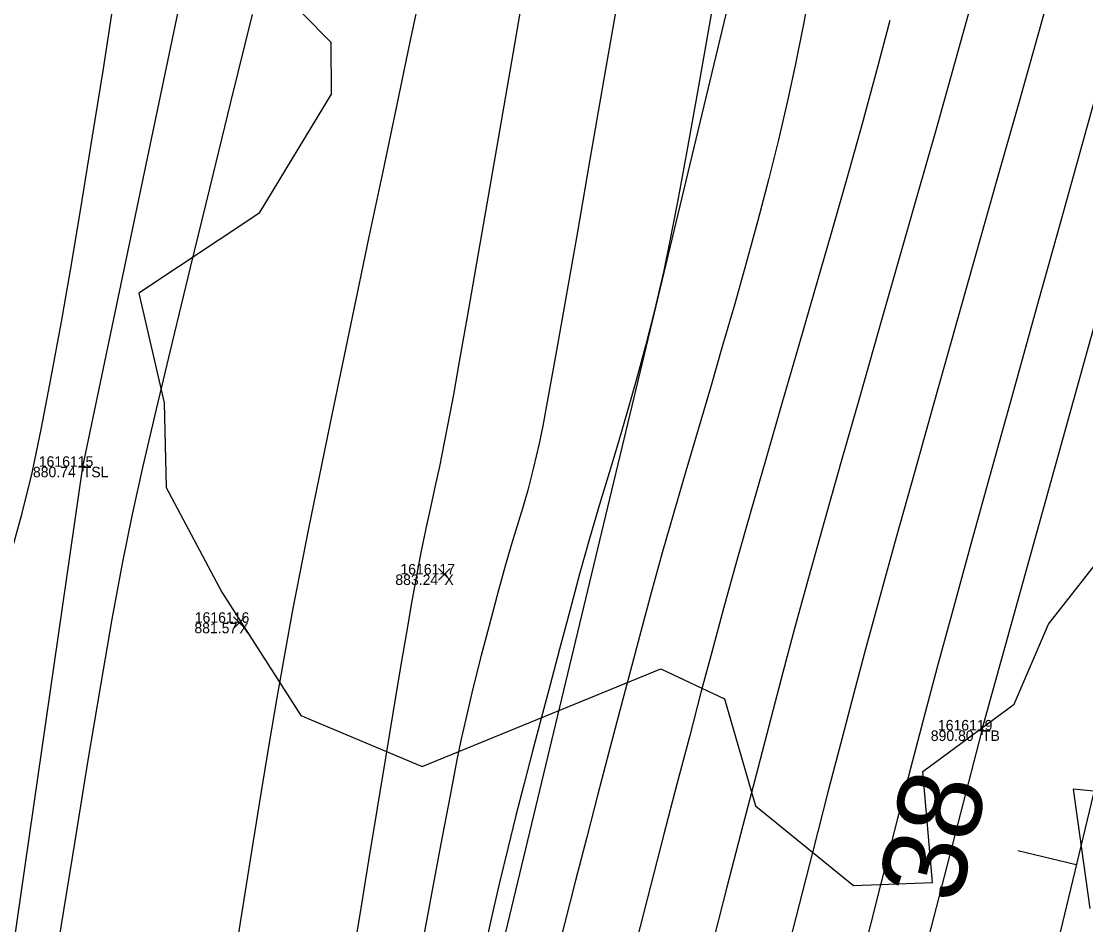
# Model space of a CAD drawing. Extents: x 1957117 to 1971063, y 701601 to 715861.
# Drawn here: x 1963216.28 to 1963251.82, y 705740.89 to 705771.05 of the extents above; entities that cross this region are included whole.
import ezdxf

# ---------------------------------------------------------------- set-up
doc = ezdxf.new("R2010")
doc.units = 0
for name, color, linetype in [('AP_X_Lights', 7, 'Continuous'), ('DT_X_Break_Line', 7, 'Continuous'), ('DT_X_Contour_Major', 7, 'Continuous'), ('DT_X_Contour_Minor', 7, 'Continuous'), ('GE_X_CL_20', 7, 'Continuous'), ('HY_X_Water_Edge', 7, 'Continuous'), ('PV_P_Drive', 7, 'Continuous'), ('PV_P_Shoulder', 7, 'Continuous'), ('RS_Raster1', 7, 'Continuous'), ('RW_X_Esmt_RR', 7, 'Continuous'), ('SC_Scratch1', 7, 'Continuous'), ('SC_Shading5', 7, 'Continuous'), ('VG_X_Tree_Line_Rt', 7, 'Continuous')]:
    doc.layers.add(name, color=color, linetype=linetype)

msp = doc.modelspace()

# ---------------------------------------------------------------- linework, layer by layer
at = {"layer": 'AP_X_Lights'}
for p, q in [((1963230.21, 705752.387), (1963230.598, 705752.777)), ((1963230.21, 705752.777), (1963230.598, 705752.387)), ((1963223.365, 705750.775), (1963223.753, 705751.165)), ((1963223.365, 705751.165), (1963223.753, 705750.775))]:
    msp.add_line(p, q, dxfattribs=at)
at = {"layer": 'DT_X_Break_Line'}
for points in [[(1963218.329, 705756.178), (1963229.265, 705808.356), (1963234.8, 705853.147), (1963240.079, 705903.468), (1963258.033, 705954.684), (1963270.287, 705999.321), (1963276.323, 706049.345), (1963291.502, 706096.678), (1963290.138, 706117.655), (1963319.921, 706191.295), (1963330.374, 706242.631), (1963344.413, 706289.409), (1963345.772, 706340.009), (1963383.117, 706434.704), (1963392.11, 706487.426), (1963408.164, 706535.687), (1963423.633, 706582.721), (1963435.242, 706630.63), (1963443.084, 706680.696), (1963464.732, 706726.815), (1963480.654, 706774.214), (1963508.465, 706799.669), (1963511.002, 706809.48)], [(1963248.355, 705747.376), (1963261.829, 705795.923), (1963267.581, 705840.559), (1963287.153, 705892.264), (1963291.083, 705944.763), (1963301.574, 705996.211), (1963311.528, 706039.027), (1963334.717, 706086.75), (1963331.957, 706106.508), (1963348.786, 706182.796), (1963365.664, 706223.934), (1963373.462, 706281.461), (1963387.853, 706330.217), (1963397.264, 706379.501), (1963407.696, 706427.592), (1963426.755, 706477.16), (1963442.136, 706524.014), (1963446.007, 706569.971), (1963489.391, 706666.839), (1963500.526, 706701.536)], [(1963059.618, 705072.384), (1963067.267, 705121.949), (1963084.435, 705172.155), (1963089.948, 705219.61), (1963104.733, 705267.194), (1963118.935, 705315.406), (1963122.413, 705362.88), (1963135.773, 705414.457), (1963142.701, 705466.671), (1963157.121, 705507.344), (1963171.033, 705561.75), (1963190.964, 705600.578), (1963199.065, 705656.682), (1963210.848, 705704.455), (1963218.329, 705756.178)], [(1963248.355, 705747.376), (1963235.759, 705698.829), (1963221.229, 705652.053), (1963207.844, 705601.615), (1963200.47, 705556.329), (1963185.917, 705507.018), (1963175.154, 705452.621), (1963160.398, 705408.434), (1963150.566, 705354.43), (1963137.351, 705306.484), (1963127.753, 705261.545), (1963117.087, 705216.019), (1963104.746, 705164.3), (1963091.28, 705116.393), (1963081.686, 705067.168)]]:
    msp.add_lwpolyline(points, dxfattribs=at)
at = {"layer": 'DT_X_Contour_Major'}
for points in [[(1963253.53, 705773.47), (1963252.693, 705770.482), (1963251.848, 705767.465), (1963251.009, 705764.466), (1963250.189, 705761.531), (1963249.403, 705758.709), (1963248.663, 705756.046), (1963247.984, 705753.59), (1963247.379, 705751.387), (1963246.862, 705749.484), (1963246.446, 705747.93), (1963246.036, 705746.364), (1963245.537, 705744.431), (1963244.96, 705742.179), (1963244.318, 705739.658), (1963243.623, 705736.92), (1963242.888, 705734.012), (1963242.124, 705730.985), (1963241.346, 705727.89), (1963240.563, 705724.775), (1963239.791, 705721.69), (1963239.039, 705718.686), (1963238.322, 705715.813)], [(1963253.53, 705773.47), (1963252.693, 705770.482), (1963251.848, 705767.465), (1963251.009, 705764.466), (1963250.189, 705761.531), (1963249.403, 705758.709), (1963248.663, 705756.046), (1963247.984, 705753.59), (1963247.379, 705751.387), (1963246.862, 705749.484), (1963246.446, 705747.93), (1963246.036, 705746.364), (1963245.537, 705744.431), (1963244.96, 705742.179), (1963244.318, 705739.658), (1963243.623, 705736.92), (1963242.888, 705734.012), (1963242.124, 705730.985), (1963241.346, 705727.89), (1963240.563, 705724.775), (1963239.791, 705721.69), (1963239.039, 705718.686), (1963238.322, 705715.813)], [(1963239.664, 705773.319), (1963239.246, 705770.907), (1963238.856, 705768.69), (1963238.501, 705766.713), (1963238.189, 705765.021), (1963237.926, 705763.659), (1963237.719, 705762.671), (1963237.42, 705761.392), (1963237.122, 705760.211), (1963236.822, 705759.102), (1963236.521, 705758.042), (1963236.216, 705757.007), (1963235.906, 705755.973), (1963235.589, 705754.916), (1963235.265, 705753.812), (1963234.932, 705752.638), (1963234.588, 705751.369), (1963234.25, 705750.093), (1963233.933, 705748.901), (1963233.633, 705747.771), (1963233.346, 705746.681), (1963233.068, 705745.61), (1963232.795, 705744.537), (1963232.524, 705743.439), (1963232.25, 705742.297), (1963231.97, 705741.087), (1963231.678, 705739.789)], [(1963239.664, 705773.319), (1963239.246, 705770.907), (1963238.856, 705768.69), (1963238.501, 705766.713), (1963238.189, 705765.021), (1963237.926, 705763.659), (1963237.719, 705762.671), (1963237.42, 705761.392), (1963237.122, 705760.211), (1963236.822, 705759.102), (1963236.521, 705758.042), (1963236.216, 705757.007), (1963235.906, 705755.973), (1963235.589, 705754.916), (1963235.265, 705753.812), (1963234.932, 705752.638), (1963234.588, 705751.369), (1963234.25, 705750.093), (1963233.933, 705748.901), (1963233.633, 705747.771), (1963233.346, 705746.681), (1963233.068, 705745.61), (1963232.795, 705744.537), (1963232.524, 705743.439), (1963232.25, 705742.297), (1963231.97, 705741.087), (1963231.678, 705739.789)]]:
    msp.add_lwpolyline(points, dxfattribs=at)
at = {"layer": 'DT_X_Contour_Minor'}
for points in [[(1963251.016, 705773.406), (1963250.321, 705770.94), (1963249.605, 705768.403), (1963248.879, 705765.834), (1963248.154, 705763.27), (1963247.441, 705760.748), (1963246.753, 705758.306), (1963246.1, 705755.983), (1963245.494, 705753.814), (1963244.947, 705751.839), (1963244.47, 705750.094), (1963244.074, 705748.617), (1963243.685, 705747.133), (1963243.225, 705745.364), (1963242.706, 705743.351), (1963242.137, 705741.134), (1963241.528, 705738.752)], [(1963251.016, 705773.406), (1963250.321, 705770.94), (1963249.605, 705768.403), (1963248.879, 705765.834), (1963248.154, 705763.27), (1963247.441, 705760.748), (1963246.753, 705758.306), (1963246.1, 705755.983), (1963245.494, 705753.814), (1963244.947, 705751.839), (1963244.47, 705750.094), (1963244.074, 705748.617), (1963243.685, 705747.133), (1963243.225, 705745.364), (1963242.706, 705743.351), (1963242.137, 705741.134), (1963241.528, 705738.752)], [(1963233.229, 705773.1), (1963232.743, 705770.289), (1963232.286, 705767.644), (1963231.864, 705765.213), (1963231.487, 705763.045), (1963231.163, 705761.187), (1963230.9, 705759.688), (1963230.706, 705758.595), (1963230.59, 705757.958), (1963230.402, 705756.993), (1963230.236, 705756.192), (1963230.084, 705755.491), (1963229.938, 705754.822), (1963229.786, 705754.12), (1963229.622, 705753.32), (1963229.436, 705752.354), (1963229.306, 705751.632), (1963229.137, 705750.644), (1963228.932, 705749.428), (1963228.698, 705748.021), (1963228.44, 705746.46), (1963228.164, 705744.784), (1963227.875, 705743.031), (1963227.579, 705741.237), (1963227.28, 705739.441)], [(1963233.229, 705773.1), (1963232.743, 705770.289), (1963232.286, 705767.644), (1963231.864, 705765.213), (1963231.487, 705763.045), (1963231.163, 705761.187), (1963230.9, 705759.688), (1963230.706, 705758.595), (1963230.59, 705757.958), (1963230.402, 705756.993), (1963230.236, 705756.192), (1963230.084, 705755.491), (1963229.938, 705754.822), (1963229.786, 705754.12), (1963229.622, 705753.32), (1963229.436, 705752.354), (1963229.306, 705751.632), (1963229.137, 705750.644), (1963228.932, 705749.428), (1963228.698, 705748.021), (1963228.44, 705746.46), (1963228.164, 705744.784), (1963227.875, 705743.031), (1963227.579, 705741.237), (1963227.28, 705739.441)], [(1963242.713, 705772.671), (1963242.402, 705771.011), (1963242.118, 705769.573), (1963241.866, 705768.39), (1963241.561, 705767.087), (1963241.228, 705765.753), (1963240.87, 705764.394), (1963240.492, 705763.014), (1963240.099, 705761.621), (1963239.695, 705760.221), (1963239.286, 705758.818), (1963238.875, 705757.418), (1963238.467, 705756.028), (1963238.067, 705754.654), (1963237.679, 705753.301), (1963237.308, 705751.974), (1963236.959, 705750.681), (1963236.616, 705749.381), (1963236.261, 705748.037), (1963235.898, 705746.656), (1963235.529, 705745.247), (1963235.157, 705743.816), (1963234.784, 705742.372), (1963234.414, 705740.923), (1963234.049, 705739.475)], [(1963242.713, 705772.671), (1963242.402, 705771.011), (1963242.118, 705769.573), (1963241.866, 705768.39), (1963241.561, 705767.087), (1963241.228, 705765.753), (1963240.87, 705764.394), (1963240.492, 705763.014), (1963240.099, 705761.621), (1963239.695, 705760.221), (1963239.286, 705758.818), (1963238.875, 705757.418), (1963238.467, 705756.028), (1963238.067, 705754.654), (1963237.679, 705753.301), (1963237.308, 705751.974), (1963236.959, 705750.681), (1963236.616, 705749.381), (1963236.261, 705748.037), (1963235.898, 705746.656), (1963235.529, 705745.247), (1963235.157, 705743.816), (1963234.784, 705742.372), (1963234.414, 705740.923), (1963234.049, 705739.475)], [(1963229.693, 705772.446), (1963229.256, 705770.362), (1963228.804, 705768.213), (1963228.345, 705766.031), (1963227.887, 705763.851), (1963227.436, 705761.704), (1963227.001, 705759.625), (1963226.59, 705757.646), (1963226.21, 705755.799), (1963225.869, 705754.119), (1963225.575, 705752.637), (1963225.335, 705751.388), (1963225.075, 705749.963), (1963224.812, 705748.459), (1963224.546, 705746.89), (1963224.278, 705745.272), (1963224.009, 705743.618), (1963223.739, 705741.942), (1963223.469, 705740.259)], [(1963229.693, 705772.446), (1963229.256, 705770.362), (1963228.804, 705768.213), (1963228.345, 705766.031), (1963227.887, 705763.851), (1963227.436, 705761.704), (1963227.001, 705759.625), (1963226.59, 705757.646), (1963226.21, 705755.799), (1963225.869, 705754.119), (1963225.575, 705752.637), (1963225.335, 705751.388), (1963225.075, 705749.963), (1963224.812, 705748.459), (1963224.546, 705746.89), (1963224.278, 705745.272), (1963224.009, 705743.618), (1963223.739, 705741.942), (1963223.469, 705740.259)], [(1963215.84, 705752.94), (1963216.304, 705754.63), (1963216.635, 705755.979), (1963216.951, 705757.479), (1963217.279, 705759.17), (1963217.617, 705761.021), (1963217.961, 705762.999), (1963218.31, 705765.075), (1963218.659, 705767.218), (1963219.007, 705769.396), (1963219.35, 705771.578)], [(1963215.84, 705752.94), (1963216.304, 705754.63), (1963216.635, 705755.979), (1963216.951, 705757.479), (1963217.279, 705759.17), (1963217.617, 705761.021), (1963217.961, 705762.999), (1963218.31, 705765.075), (1963218.659, 705767.218), (1963219.007, 705769.396), (1963219.35, 705771.578)], [(1963236.203, 705771.865), (1963235.719, 705769.062), (1963235.264, 705766.432), (1963234.845, 705764.022), (1963234.47, 705761.881), (1963234.148, 705760.056), (1963233.885, 705758.594), (1963233.691, 705757.544), (1963233.572, 705756.952), (1963233.372, 705756.103), (1963233.188, 705755.401), (1963233.013, 705754.789), (1963232.836, 705754.206), (1963232.65, 705753.596), (1963232.446, 705752.899), (1963232.216, 705752.057), (1963231.991, 705751.21), (1963231.801, 705750.501), (1963231.634, 705749.873), (1963231.478, 705749.27), (1963231.321, 705748.634), (1963231.151, 705747.91), (1963230.956, 705747.041), (1963230.825, 705746.396), (1963230.596, 705745.207), (1963230.28, 705743.537), (1963229.888, 705741.447), (1963229.43, 705738.997)], [(1963236.203, 705771.865), (1963235.719, 705769.062), (1963235.264, 705766.432), (1963234.845, 705764.022), (1963234.47, 705761.881), (1963234.148, 705760.056), (1963233.885, 705758.594), (1963233.691, 705757.544), (1963233.572, 705756.952), (1963233.372, 705756.103), (1963233.188, 705755.401), (1963233.013, 705754.789), (1963232.836, 705754.206), (1963232.65, 705753.596), (1963232.446, 705752.899), (1963232.216, 705752.057), (1963231.991, 705751.21), (1963231.801, 705750.501), (1963231.634, 705749.873), (1963231.478, 705749.27), (1963231.321, 705748.634), (1963231.151, 705747.91), (1963230.956, 705747.041), (1963230.825, 705746.396), (1963230.596, 705745.207), (1963230.28, 705743.537), (1963229.888, 705741.447), (1963229.43, 705738.997)], [(1963248.032, 705771.75), (1963247.441, 705769.643), (1963246.821, 705767.451), (1963246.182, 705765.205), (1963245.535, 705762.939), (1963244.892, 705760.687), (1963244.262, 705758.481), (1963243.657, 705756.354), (1963243.088, 705754.34), (1963242.565, 705752.472), (1963242.1, 705750.783), (1963241.703, 705749.305), (1963241.312, 705747.82), (1963240.866, 705746.109), (1963240.372, 705744.206), (1963239.841, 705742.147), (1963239.281, 705739.967)], [(1963248.032, 705771.75), (1963247.441, 705769.643), (1963246.821, 705767.451), (1963246.182, 705765.205), (1963245.535, 705762.939), (1963244.892, 705760.687), (1963244.262, 705758.481), (1963243.657, 705756.354), (1963243.088, 705754.34), (1963242.565, 705752.472), (1963242.1, 705750.783), (1963241.703, 705749.305), (1963241.312, 705747.82), (1963240.866, 705746.109), (1963240.372, 705744.206), (1963239.841, 705742.147), (1963239.281, 705739.967)], [(1963223.991, 705771.271), (1963223.265, 705768.343), (1963222.569, 705765.512), (1963221.914, 705762.828), (1963221.313, 705760.341), (1963220.78, 705758.098), (1963220.328, 705756.15), (1963219.969, 705754.545), (1963219.656, 705753.003), (1963219.304, 705751.094), (1963218.918, 705748.872), (1963218.502, 705746.385), (1963218.061, 705743.685), (1963217.6, 705740.822), (1963217.124, 705737.848), (1963216.637, 705734.814), (1963216.144, 705731.769), (1963215.651, 705728.766), (1963215.16, 705725.854), (1963214.678, 705723.085), (1963214.209, 705720.51), (1963213.758, 705718.178), (1963213.329, 705716.142)], [(1963223.991, 705771.271), (1963223.265, 705768.343), (1963222.569, 705765.512), (1963221.914, 705762.828), (1963221.313, 705760.341), (1963220.78, 705758.098), (1963220.328, 705756.15), (1963219.969, 705754.545), (1963219.656, 705753.003), (1963219.304, 705751.094), (1963218.918, 705748.872), (1963218.502, 705746.385), (1963218.061, 705743.685), (1963217.6, 705740.822), (1963217.124, 705737.848), (1963216.637, 705734.814), (1963216.144, 705731.769), (1963215.651, 705728.766), (1963215.16, 705725.854), (1963214.678, 705723.085), (1963214.209, 705720.51), (1963213.758, 705718.178), (1963213.329, 705716.142)], [(1963245.275, 705771.076), (1963244.832, 705769.394), (1963244.351, 705767.629), (1963243.841, 705765.802), (1963243.31, 705763.934), (1963242.766, 705762.045), (1963242.219, 705760.156), (1963241.676, 705758.289), (1963241.146, 705756.463), (1963240.639, 705754.7), (1963240.161, 705753.02), (1963239.722, 705751.444), (1963239.331, 705749.993), (1963238.973, 705748.637), (1963238.585, 705747.159), (1963238.17, 705745.578), (1963237.736, 705743.913), (1963237.287, 705742.181), (1963236.828, 705740.402)], [(1963245.275, 705771.076), (1963244.832, 705769.394), (1963244.351, 705767.629), (1963243.841, 705765.802), (1963243.31, 705763.934), (1963242.766, 705762.045), (1963242.219, 705760.156), (1963241.676, 705758.289), (1963241.146, 705756.463), (1963240.639, 705754.7), (1963240.161, 705753.02), (1963239.722, 705751.444), (1963239.331, 705749.993), (1963238.973, 705748.637), (1963238.585, 705747.159), (1963238.17, 705745.578), (1963237.736, 705743.913), (1963237.287, 705742.181), (1963236.828, 705740.402)]]:
    msp.add_lwpolyline(points, dxfattribs=at)
at = {"layer": 'GE_X_CL_20'}
msp.add_line((1963251.503, 705742.887), (1963249.558, 705743.354), dxfattribs=at)
msp.add_lwpolyline([(1963418.3, 706437.397), (1962895.621, 704261.062)], dxfattribs=at)
at = {"layer": 'HY_X_Water_Edge'}
msp.add_spline([(1963191.723, 701994.048), (1963062.047, 702441.167), (1962863.491, 703169.356), (1962827.53, 703438.691), (1962823.213, 703537.412), (1962817.962, 703593.874), (1962817.97, 703697.316), (1962828.582, 703804.235), (1962836.461, 703844.734), (1962850.687, 703896.004), (1962867.251, 703938.846), (1962873.848, 703992.355), (1962884.135, 704091.371), (1962891.241, 704140.854), (1962897.382, 704180.529), (1962905.467, 704230.979), (1962943.949, 704328.022), (1962948.537, 704378.842), (1962964.114, 704426.264), (1963004.885, 704570.73), (1963042.054, 704716.522), (1963062.038, 704814.417), (1963072.171, 704860.237), (1963090.023, 704956.798), (1963107.066, 705031.783), (1963133.773, 705105.742), (1963148.685, 705206.74), (1963175.48, 705301.059), (1963191.635, 705353.417), (1963210.988, 705447.286), (1963219.532, 705497.27), (1963230.124, 705549.475), (1963251.052, 705591.159), (1963275.289, 705693.429), (1963292.982, 705784.032), (1963302.841, 705839.645), (1963335.126, 705936.766), (1963359.752, 706046.75), (1963389.133, 706177.299), (1963417.827, 706273.456), (1963475.868, 706451.902), (1963533.782, 706640.53), (1963553.86, 706696.984), (1963580.184, 706715.425), (1963609.172, 706718.73), (1963617.062, 706714.691), (1963619.447, 706694.678), (1963564.282, 706533.07), (1963531.853, 706395.229), (1963434.4, 706006.96), (1963354.09, 705679.186), (1963237.513, 705206.07), (1963167.369, 704892.962), (1963059.145, 704434.176), (1962907.914, 703908.742), (1962877.458, 703703.326), (1962898.357, 703412.121), (1962942.65, 703052.267), (1963048.963, 702674.866), (1963191.468, 702189.666), (1963245.396, 702019.832)], degree=3, dxfattribs=at)
at = {"layer": 'PV_P_Drive'}
for p, q in [((1963218.329, 705756.324), (1963218.329, 705756.032)), ((1963218.183, 705756.178), (1963218.475, 705756.178)), ((1963218.329, 705756.178), (1963218.329, 705756.178)), ((1963248.355, 705747.522), (1963248.355, 705747.23)), ((1963248.209, 705747.376), (1963248.501, 705747.376)), ((1963248.355, 705747.376), (1963248.355, 705747.376))]:
    msp.add_line(p, q, dxfattribs=at)
at = {"layer": 'RW_X_Esmt_RR'}
msp.add_lwpolyline([(1962866.45, 704268.068), (1963123.345, 705337.727), (1963135.496, 705336.937), (1963400.797, 706441.601)], dxfattribs=at)
at = {"layer": 'SC_Shading5'}
for points in [[(1963026.912, 704294.121), (1963138.818, 704737.794), (1963251.679, 705213.963), (1963374.306, 705730.111), (1963454.783, 706045.593), (1963517.244, 706296.713), (1963562.763, 706479.256), (1963580.13, 706553.799), (1963589.678, 706586.994)], [(1963609.915, 706579.703), (1963587.283, 706499.153), (1963552.056, 706354.005), (1963480.911, 706069.234), (1963357.401, 705576.869), (1963272.751, 705226.931), (1963210.247, 704956.481), (1963044.97, 704288.881)]]:
    msp.add_spline(points, degree=3, dxfattribs=at)
at = {"layer": 'VG_X_Tree_Line_Rt'}
for points in [[(1963223.781, 705773.218), (1963226.609, 705770.346), (1963226.624, 705768.614), (1963224.211, 705764.632), (1963220.201, 705761.974), (1963221.046, 705758.308), (1963221.115, 705755.482), (1963222.974, 705751.987), (1963225.607, 705747.874), (1963229.667, 705746.177), (1963237.627, 705749.434), (1963239.757, 705748.435), (1963240.795, 705744.861), (1963244.066, 705742.197), (1963246.7, 705742.302), (1963246.377, 705746.002), (1963249.433, 705748.258), (1963250.574, 705750.924), (1963254.108, 705755.419)], [(1963255.419, 705745.031), (1963251.406, 705745.413), (1963251.958, 705741.432)]]:
    msp.add_lwpolyline(points, dxfattribs=at)

# ---------------------------------------------------------------- texts
at = {"layer": 'GE_X_CL_20'}
msp.add_text('38', height=2.8, rotation=76.4953, dxfattribs=at).set_placement((1963247.575, 705741.522))
at = {"layer": 'PV_P_Shoulder'}
for s, p in [('880.74', (1963216.665, 705755.828)), ('883.24', (1963228.767, 705752.232)), ('881.57', (1963222.057, 705750.62)), ('890.80', (1963246.646, 705747.026))]:
    msp.add_text(s, height=0.35, dxfattribs=at).set_placement(p)
at = {"layer": 'RS_Raster1'}
for s, p in [('1616115', (1963216.861, 705756.178)), ('1616117', (1963228.936, 705752.582)), ('1616116', (1963222.069, 705750.97)), ('1616119', (1963246.884, 705747.376))]:
    msp.add_text(s, height=0.35, dxfattribs=at).set_placement(p)
at = {"layer": 'SC_Scratch1'}
for s, p in [('TSL', (1963218.329, 705755.828)), ('X', (1963230.404, 705752.232)), ('X', (1963223.559, 705750.62)), ('TB', (1963248.355, 705747.026))]:
    msp.add_text(s, height=0.35, dxfattribs=at).set_placement(p)

doc.saveas('drawing.dxf')
